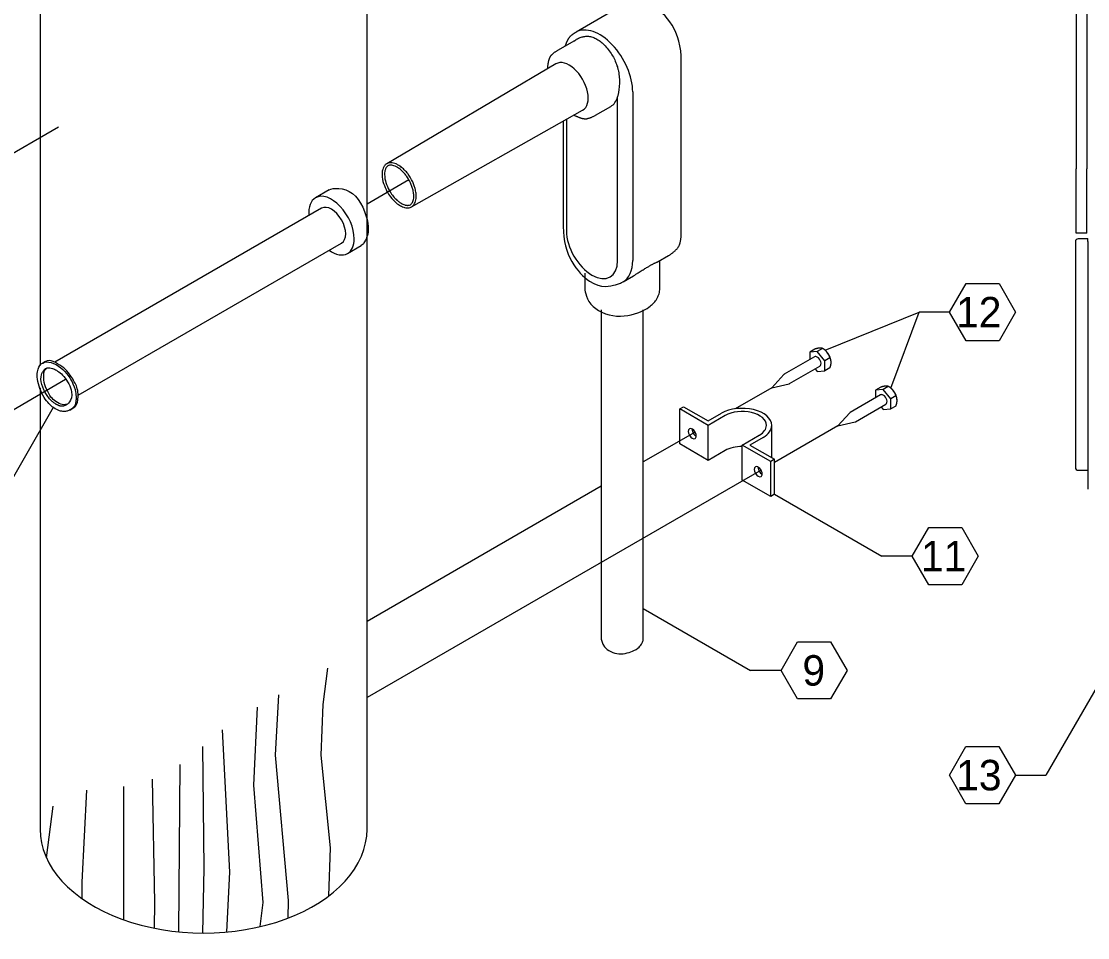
# Model space of a CAD drawing. Extents: x 99862 to 103151, y 100000 to 105076.
# Drawn here: x 100805 to 101365, y 104347 to 104827 of the extents above; entities that cross this region are included whole.
import ezdxf

# ---------------------------------------------------------------- set-up
doc = ezdxf.new("R2010")
doc.units = 0
for name, color, linetype in [('Level 13', 7, 'Continuous'), ('Level 15', 7, 'Continuous'), ('Level 16', 7, 'Continuous'), ('Level 20', 7, 'Continuous'), ('Level 21', 7, 'Continuous'), ('Level 23', 7, 'Continuous'), ('Level 27', 7, 'Continuous'), ('Level 28', 7, 'Continuous'), ('Level 31', 7, 'Continuous'), ('Level 33', 7, 'Continuous'), ('Level 41', 7, 'Continuous')]:
    doc.layers.add(name, color=color, linetype=linetype)

msp = doc.modelspace()

# ---------------------------------------------------------------- linework, layer by layer
at = {"layer": 'Level 13'}
for p, q in [((101120.49, 104835.56), (101096.62, 104821.78)), ((101095.44, 104817.14), (101087.15, 104812.36)), ((101151.84, 104718.09), (101151.84, 104806.5)), ((101118.81, 104790.2), (101118.38, 104787.89)), ((101118.38, 104702.01), (101118.38, 104787.89)), ((101126.33, 104790.43), (101126.33, 104702.01)), ((101106.84, 104778.26), (101114.79, 104782.85)), ((101091.53, 104775.91), (101091.53, 104717.52)), ((101089.88, 104774.96), (101089.88, 104719.81)), ((101139.65, 104701.38), (101145.1, 104704.53)), ((101145.14, 104704.55), (101145.62, 104704.85)), ((101145.62, 104704.85), (101145.79, 104704.96)), ((101140.55, 104687.37), (101140.55, 104701.9)), ((101101.17, 104695.41), (101101.17, 104687.37)), ((101121.23, 104690.75), (101126.71, 104693.91)), ((101140.55, 104687.18), (101140.55, 104687.38))]:
    msp.add_line(p, q, dxfattribs=at)
for centre, major_axis, start_param, end_param in [((101108.93, 104800.47), (-12.3, 21.31), 3.926991, 6.282516), ((101093.02, 104793.01), (7.03, -12.18), 6.283185, 9.424778), ((101104.95, 104799.9), (9.84, -17.05), 0, 0.517335), ((101104.95, 104709.76), (9.49, -16.44), 3.926991, 7.068583), ((101108.93, 104712.06), (-12.3, 21.31), 3.140924, 3.926991)]:
    msp.add_ellipse(centre, major_axis=major_axis, ratio=0.57735, start_param=start_param, end_param=end_param, dxfattribs=at)
for points, degree in [([(101151.84, 104806.5), (101152.06, 104822.03), (101135.62, 104841.83), (101121.8, 104836.21), (101121.6, 104836.13)], 3), ([(101096.64, 104821.79), (101093.88, 104820.23), (101091.88, 104817.56), (101090.86, 104814.51)], 2), ([(101095.44, 104817.14), (101104.39, 104823.57), (101121.18, 104803.6), (101118.81, 104790.2)], 2), ([(101087.13, 104812.34), (101083.69, 104810.37), (101081.82, 104806.61), (101081.48, 104802.59)], 2), ([(101095.54, 104778.23), (101099.2, 104776.49), (101103.16, 104776.22), (101106.84, 104778.25)], 2), ([(101089.88, 104719.81), (101089.69, 104704.95), (101105.07, 104685.67), (101119.4, 104689.86), (101120.41, 104690.33), (101120.93, 104690.58)], 3), ([(101145.79, 104704.96), (101149.92, 104707.73), (101151.89, 104712.77), (101151.84, 104718.09)], 2), ([(101126.71, 104693.91), (101132.46, 104697.57), (101138.16, 104700.87), (101139.67, 104701.39)], 2), ([(101101.17, 104687.37), (101101.16, 104687.06), (101101.79, 104678.11), (101117.89, 104670.7), (101133.74, 104675.82), (101137.87, 104680.23), (101138.84, 104681.55), (101139.62, 104682.97), (101140.18, 104684.49), (101140.48, 104685.93), (101140.53, 104686.83), (101140.55, 104687.18)], 3)]:
    msp.add_open_spline(points, degree=degree, dxfattribs=at)
at = {"layer": 'Level 15'}
for p, q in [((101227.28, 104654.9), (101276.7, 104674.85)), ((101261.9, 104634.91), (101276.7, 104674.85)), ((101292.7, 104674.85), (101276.7, 104674.85)), ((100822.1, 104624.87), (100721.67, 104450.91)), ((101200.74, 104579.29), (101257.03, 104546.79)), ((101426.72, 104576.54), (101343.2, 104431.88)), ((101273.03, 104546.79), (101257.03, 104546.79)), ((101131.89, 104519.34), (101188.19, 104486.84)), ((101131.89, 104519.34), (101188.19, 104486.84)), ((101204.19, 104486.84), (101188.19, 104486.84)), ((101204.19, 104486.84), (101188.19, 104486.84)), ((101327.2, 104431.88), (101343.2, 104431.88))]:
    msp.add_line(p, q, dxfattribs=at)
at = {"layer": 'Level 16'}
for p, q in [((100824.93, 104771.97), (100695.86, 104697.45)), ((101008.83, 104744.29), (100986.88, 104731.52)), ((100828.58, 104639.5), (100696.72, 104562.84)), ((101199.34, 104635.21), (101180.15, 104624.13)), ((101233.96, 104615.22), (101200.74, 104596.04)), ((101159.05, 104611.95), (101131.89, 104596.27)), ((101193.67, 104591.96), (100986.88, 104472.57)), ((101109.75, 104583.48), (100986.88, 104512.55))]:
    msp.add_line(p, q, dxfattribs=at)
at = {"layer": 'Level 20'}
for points in [[(101292.7, 104674.85), (101301.36, 104689.85), (101318.68, 104689.85), (101327.33, 104674.85), (101318.68, 104659.85), (101301.36, 104659.85), (101292.7, 104674.85)], [(101273.03, 104546.79), (101281.69, 104561.79), (101299.01, 104561.79), (101307.66, 104546.79), (101299.01, 104531.79), (101281.69, 104531.79), (101273.03, 104546.79)], [(101204.19, 104486.84), (101212.85, 104501.83), (101230.17, 104501.83), (101238.81, 104486.84), (101230.17, 104471.84), (101212.85, 104471.84), (101204.19, 104486.84)], [(101292.58, 104431.88), (101301.24, 104446.88), (101318.56, 104446.88), (101327.2, 104431.88), (101318.56, 104416.89), (101301.24, 104416.89), (101292.58, 104431.88)]]:
    msp.add_lwpolyline(points, dxfattribs=at)
at = {"layer": 'Level 21'}
for p, q in [((100966.92, 104739.02), (100959.77, 104734.89)), ((100962.93, 104729.41), (100822.99, 104648.61)), ((100835.21, 104631.31), (100973.48, 104711.14)), ((100976.64, 104705.66), (100983.8, 104709.79))]:
    msp.add_line(p, q, dxfattribs=at)
for major_axis, start_param, end_param in [((8.44, -14.61), 0.785398, 3.141593), ((8.44, -14.61), 3.141593, 4.037256), ((-5.27, 9.13), 3.141593, 6.283185), ((8.44, -14.61), 0, 0.785398), ((8.44, -14.61), 5.387519, 6.283185)]:
    msp.add_ellipse((100968.21, 104720.27), major_axis=major_axis, ratio=0.57735, start_param=start_param, end_param=end_param, dxfattribs=at)
msp.add_open_spline([(100966.92, 104739.02), (100968.8, 104740.12), (100980.76, 104741.03), (100989.3, 104719.13), (100985.55, 104711.6), (100984.81, 104710.48), (100984.11, 104710), (100983.8, 104709.79)], degree=3, dxfattribs=at)
at = {"layer": 'Level 23'}
for p, q in [((100817.7, 104648.77), (100816.61, 104648.14)), ((100830.84, 104623.5), (100831.93, 104624.13))]:
    msp.add_line(p, q, dxfattribs=at)
for points, degree in [([(100830.84, 104623.5), (100830.56, 104623.34), (100829.49, 104622.84), (100827.76, 104622.6), (100825.49, 104622.99), (100822.65, 104624.23), (100817.12, 104629.04), (100812.83, 104640.49), (100814.61, 104646.86), (100816.46, 104648.04), (100816.6, 104648.13), (100816.61, 104648.14)], 3), ([(100816.61, 104648.14), (100818.92, 104649.62), (100827.02, 104646.68), (100833.5, 104636.4), (100834.03, 104631.58), (100834.11, 104630.88), (100834.12, 104630.43), (100834.12, 104630.21)], 3), ([(100835.22, 104630.84), (100835.22, 104633.91), (100833.96, 104637.45), (100829.89, 104643.66), (100827.11, 104646.34), (100821.85, 104649.38), (100819.4, 104649.75), (100817.7, 104648.77)], 3), ([(100823.39, 104626.69), (100822.95, 104626.94), (100822.31, 104627.38), (100820.85, 104628.63), (100819.72, 104629.97), (100816.19, 104635.36), (100815.28, 104641.43), (100817.03, 104644.18), (100817.34, 104644.6), (100817.7, 104644.95), (100817.98, 104645.13), (100818.12, 104645.21)], 3), ([(100817.14, 104640.95), (100817.14, 104642.99), (100817.7, 104644.59), (100818.7, 104645.48)], 2), ([(100829.58, 104626.62), (100828.12, 104626.05), (100826.28, 104626.28), (100822.44, 104628.49), (100820.53, 104630.67), (100817.89, 104635.73), (100817.14, 104638.59), (100817.14, 104640.95)], 3), ([(100818.12, 104645.22), (100818.67, 104645.54), (100819.73, 104645.77), (100822.21, 104645.34), (100827.82, 104642.15), (100833.08, 104632.27), (100830.59, 104627.18), (100829.12, 104626.3), (100829.06, 104626.26)], 3), ([(100834.12, 104630.21), (100834.14, 104627.17), (100832.9, 104624.69), (100830.87, 104623.52)], 2), ([(100831.92, 104624.13), (100831.92, 104624.13), (100831.92, 104624.13), (100831.92, 104624.13), (100833.95, 104625.3), (100835.22, 104627.77), (100835.22, 104630.84)], 3), ([(100829.06, 104626.26), (100827.53, 104625.37), (100825.42, 104625.51), (100823.39, 104626.69)], 2)]:
    msp.add_open_spline(points, degree=degree, dxfattribs=at)
at = {"layer": 'Level 27'}
for p, q in [((101085.99, 104805.19), (100997.2, 104752.77)), ((101010.27, 104730.15), (101100.05, 104780.83)), ((101109.75, 104676), (101109.75, 104503.53)), ((101131.89, 104503.68), (101131.89, 104676))]:
    msp.add_line(p, q, dxfattribs=at)
for points in [[(100997.2, 104752.77), (100996.84, 104752.56), (100996.51, 104752.29), (100995.93, 104751.62), (100995.67, 104751.21), (100995.04, 104749.81), (100994.79, 104748.61), (100994.79, 104747.2)], [(101010.27, 104730.15), (101010.64, 104730.36), (101010.97, 104730.64), (101011.55, 104731.31), (101011.8, 104731.72), (101012.43, 104733.12), (101012.68, 104734.31), (101012.68, 104736.39), (101012.62, 104737.13), (101012.38, 104738.67), (101012.2, 104739.49), (101011.48, 104741.9), (101010.77, 104743.51), (101009.03, 104746.53), (101007.98, 104747.95), (101006.25, 104749.78), (101005.64, 104750.34), (101004.42, 104751.32), (101003.81, 104751.74), (101002.02, 104752.78), (101000.86, 104753.17), (100999.33, 104753.32), (100998.85, 104753.3), (100997.98, 104753.13), (100997.57, 104752.99), (100997.2, 104752.77)], [(100994.79, 104747.2), (100994.79, 104745.1), (100995.34, 104742.66), (100997.43, 104737.84), (100998.92, 104735.56), (101002.38, 104731.91), (101004.27, 104730.62), (101006.87, 104729.72), (101007.67, 104729.6), (101009.09, 104729.66), (101009.72, 104729.83), (101010.27, 104730.15)], [(100997.85, 104751.65), (100997.61, 104751.52), (100997.4, 104751.34), (100996.99, 104750.87), (100996.8, 104750.58), (100996.3, 104749.48), (100996.08, 104748.46), (100996.08, 104747.2)], [(100996.08, 104747.2), (100996.08, 104745.33), (100996.58, 104743.04), (100998.55, 104738.5), (100999.98, 104736.33), (101002.4, 104733.77), (101003.24, 104733.05), (101004.89, 104731.91), (101005.69, 104731.5), (101006.79, 104731.12), (101007.14, 104731.03), (101007.78, 104730.92), (101008.07, 104730.91), (101008.86, 104730.94), (101009.26, 104731.06), (101009.62, 104731.27)], [(101009.62, 104731.27), (101009.86, 104731.41), (101010.08, 104731.58), (101010.48, 104732.05), (101010.67, 104732.35), (101011.16, 104733.44), (101011.38, 104734.46), (101011.39, 104736.32), (101011.34, 104736.99), (101011.11, 104738.41), (101010.94, 104739.17), (101010.27, 104741.42), (101009.61, 104742.95), (101007.96, 104745.8), (101006.97, 104747.14), (101005.35, 104748.85), (101004.79, 104749.38), (101003.66, 104750.28), (101003.11, 104750.66), (101001.5, 104751.58), (101000.5, 104751.9), (100999.31, 104752.02), (100998.96, 104752.01), (100998.35, 104751.89), (100998.09, 104751.8), (100997.85, 104751.65)], [(101109.75, 104503.78), (101109.74, 104503.61), (101110.09, 104498.57), (101119.15, 104494.4), (101128.06, 104497.29), (101130.39, 104499.77), (101130.93, 104500.51), (101131.37, 104501.31), (101131.69, 104502.16), (101131.86, 104502.97), (101131.88, 104503.48), (101131.89, 104503.68)]]:
    msp.add_open_spline(points, degree=3, dxfattribs=at)
at = {"layer": 'Level 28'}
for p, q in [((101221.9, 104655.48), (101219.23, 104653.94)), ((101223.2, 104654.29), (101219.23, 104653.94)), ((101219.23, 104653.94), (101219.23, 104649.94)), ((101225.88, 104655.84), (101223.2, 104654.29)), ((101227.18, 104649.35), (101223.2, 104654.29)), ((101221.8, 104651.43), (101205.89, 104642.24)), ((101208.7, 104637.37), (101224.61, 104646.55)), ((101229.85, 104650.89), (101227.18, 104649.35)), ((101227.18, 104644.04), (101227.18, 104649.35)), ((101205.66, 104642.06), (101199.34, 104635.21)), ((101222.08, 104645.09), (101223.2, 104643.69)), ((101223.2, 104643.69), (101227.18, 104644.04)), ((101229.85, 104645.58), (101227.18, 104644.04)), ((101199.34, 104635.21), (101208.43, 104637.26)), ((101256.52, 104635.49), (101253.85, 104633.95)), ((101260.5, 104635.85), (101257.83, 104634.3)), ((101256.42, 104631.44), (101240.51, 104622.25)), ((101257.83, 104634.3), (101253.85, 104633.95)), ((101253.85, 104633.95), (101253.85, 104629.95)), ((101261.8, 104629.36), (101257.83, 104634.3)), ((101264.47, 104630.9), (101261.8, 104629.36)), ((101151.02, 104624.07), (101153.01, 104625.22)), ((101165.94, 104615.46), (101151.02, 104624.07)), ((101151.02, 104605.7), (101151.02, 104624.07)), ((101153.01, 104625.22), (101165.94, 104617.75)), ((101243.32, 104617.38), (101259.23, 104626.57)), ((101256.7, 104625.1), (101257.83, 104623.7)), ((101257.83, 104623.7), (101261.8, 104624.05)), ((101261.8, 104624.05), (101261.8, 104629.36)), ((101264.47, 104625.6), (101261.8, 104624.05)), ((101165.94, 104617.75), (101172.9, 104621.77)), ((101174.89, 104620.62), (101165.94, 104615.46)), ((101240.28, 104622.07), (101233.96, 104615.22)), ((101165.94, 104597.09), (101165.94, 104615.46)), ((101199.3, 104598.49), (101199.3, 104615.46)), ((101233.96, 104615.22), (101243.05, 104617.28)), ((101183.84, 104605.12), (101192.79, 104610.29)), ((101194.77, 104609.14), (101187.81, 104605.12)), ((101165.94, 104597.09), (101151.02, 104605.7)), ((101174.89, 104602.25), (101165.94, 104597.09)), ((101183.84, 104586.75), (101183.84, 104605.12)), ((101198.75, 104596.51), (101183.84, 104605.12)), ((101187.81, 104605.12), (101200.74, 104597.66)), ((101200.74, 104597.66), (101198.75, 104596.51)), ((101198.75, 104578.14), (101198.75, 104596.51)), ((101200.74, 104579.29), (101200.74, 104597.66)), ((101198.75, 104578.14), (101183.84, 104586.75)), ((101200.74, 104579.29), (101198.75, 104578.14))]:
    msp.add_line(p, q, dxfattribs=at)
for centre, major_axis, start_param, end_param in [((101226.49, 104650.89), (2.81, -4.87), 0.785398, 1.832596), ((101223.2, 104648.99), (1.41, -2.44), 2.356194, 3.141593), ((101223.2, 104648.99), (1.41, -2.44), 0, 2.356194), ((101207.29, 104639.8), (1.41, -2.44), 3.141593, 3.319303), ((101207.29, 104639.8), (1.41, -2.44), 6.105475, 6.283185), ((101257.83, 104629), (1.41, -2.44), 2.356194, 3.141593), ((101257.83, 104629), (1.41, -2.44), 6.283185, 8.63938), ((101261.11, 104630.9), (2.81, -4.87), 0.785398, 1.832596), ((101183.84, 104615.46), (15.47, 0), 0, 2.356194), ((101183.84, 104615.46), (-12.66, 0), 3.141593, 5.497787), ((101241.92, 104619.82), (1.41, -2.44), 3.141593, 3.319303), ((101157.58, 104611.1), (1.48, -2.56), 3.141593, 6.283185), ((101157.58, 104611.1), (1.48, -2.56), 0.785398, 3.141593), ((101159.56, 104612.25), (-1.48, 2.56), 0.738434, 0.785398), ((101159.56, 104612.25), (-1.48, 2.56), 0.785398, 2.403158), ((101183.84, 104615.46), (-12.66, 0), 2.356194, 3.141593), ((101183.84, 104615.46), (15.47, 0), 5.497787, 6.283185), ((101241.92, 104619.82), (1.41, -2.44), 6.105475, 6.283185), ((101157.58, 104611.1), (1.48, -2.56), 6.283185, 7.068583), ((101183.84, 104597.09), (-12.66, 0), 4.712389, 5.497787), ((101192.2, 104591.11), (1.48, -2.56), 3.141593, 6.283185), ((101192.2, 104591.11), (1.48, -2.56), 0.785398, 3.141593), ((101194.19, 104592.26), (-1.48, 2.56), 0.738434, 0.785398), ((101194.19, 104592.26), (-1.48, 2.56), 0.785398, 2.403158), ((101192.2, 104591.11), (1.48, -2.56), 0, 0.785398)]:
    msp.add_ellipse(centre, major_axis=major_axis, ratio=0.57735, start_param=start_param, end_param=end_param, dxfattribs=at)
for points in [[(101224.5, 104656.01), (101223.77, 104655.94), (101222.91, 104655.76), (101221.9, 104655.48)], [(101225.88, 104655.84), (101225.67, 104655.98), (101225.29, 104656.04), (101224.5, 104656.01)], [(101228.48, 104653.72), (101227.75, 104654.58), (101226.89, 104655.29), (101225.88, 104655.84)], [(101229.85, 104650.89), (101229.65, 104651.76), (101229.26, 104652.59), (101228.72, 104653.4)], [(101230.47, 104648.59), (101230.39, 104649.48), (101230.27, 104650.32), (101229.85, 104650.89)], [(101229.85, 104645.58), (101230.18, 104646.56), (101230.45, 104647.51), (101230.47, 104648.59)], [(101259.12, 104636.02), (101258.39, 104635.95), (101257.53, 104635.77), (101256.52, 104635.49)], [(101260.5, 104635.85), (101260.29, 104635.99), (101259.91, 104636.06), (101259.12, 104636.02)], [(101263.1, 104633.73), (101262.37, 104634.59), (101261.51, 104635.3), (101260.5, 104635.85)], [(101264.47, 104630.9), (101264.27, 104631.77), (101263.88, 104632.6), (101263.34, 104633.41)], [(101265.09, 104628.6), (101265.01, 104629.49), (101264.89, 104630.33), (101264.47, 104630.9)], [(101264.47, 104625.6), (101264.8, 104626.57), (101265.07, 104627.53), (101265.09, 104628.6)]]:
    msp.add_open_spline(points, degree=2, dxfattribs=at)
at = {"layer": 'Level 31'}
for p, q in [((100815.22, 105009.95), (100815.22, 104646.8)), ((100986.88, 104403.51), (100986.88, 105009.95)), ((100815.22, 104635.07), (100815.22, 104403.51))]:
    msp.add_line(p, q, dxfattribs=at)
for points in [[(100966.84, 104368.5), (100967.67, 104393.71), (100962.87, 104442.43), (100963.83, 104468.91), (100966.23, 104487.95)], [(100945.4, 104356.84), (100945.66, 104366.07), (100938.87, 104442.43), (100940.5, 104474.04)], [(100930.81, 104352.38), (100932.33, 104365.05), (100927.36, 104426.55), (100929.39, 104467.59)], [(100913.29, 104349.56), (100914.88, 104381), (100911.05, 104455.64)], [(100900.62, 104349), (100901.38, 104383.12), (100900.67, 104446.85)], [(100888.1, 104349.62), (100888.77, 104437.46)], [(100875.37, 104351.5), (100875.47, 104365.11), (100874.31, 104429.79)], [(100837.28, 104367.02), (100837.4, 104375.7), (100839.85, 104423.95)], [(100859.15, 104355.93), (100859.15, 104425.97)], [(100818.54, 104388.49), (100822.03, 104415.56)]]:
    msp.add_lwpolyline(points, dxfattribs=at)
msp.add_ellipse((100901.05, 104403.51), major_axis=(85.83, 0), ratio=0.635085, start_param=3.14158, end_param=6.283185, dxfattribs=at)
at = {"layer": 'Level 33'}
for p, q in [((101365.15, 104711.9), (101365.15, 104713.46)), ((101358.71, 104711.9), (101358.71, 104708.44)), ((101358.73, 104708.44), (101358.73, 104593.31)), ((101365.15, 104713.3), (101360.12, 104713.3)), ((101365.15, 104711.9), (101365.15, 104659.4)), ((101365.15, 104659.4), (101365.15, 104591.08)), ((101360.13, 104591.9), (101365.15, 104591.9)), ((101365.15, 104591.08), (101365.15, 104582.84)), ((101365.15, 104582.84), (101365.15, 104581.9))]:
    msp.add_line(p, q, dxfattribs=at)
for centre, start, end in [((101360.12, 104711.9), 90, 180), ((101360.13, 104593.31), 180, 270)]:
    msp.add_arc(centre, 1.41, start, end, dxfattribs=at)
at = {"layer": 'Level 41'}
for p, q in [((101359.17, 105031.74), (101359.17, 104750.04)), ((101364.79, 105031.74), (101364.79, 104750.04)), ((101359.17, 104716.29), (101359.17, 104750.04)), ((101364.79, 104716.29), (101364.79, 104750.04)), ((101364.79, 104716.29), (101359.17, 104716.29))]:
    msp.add_line(p, q, dxfattribs=at)

# ---------------------------------------------------------------- texts
at = {"layer": 'Level 20'}
for s, p in [('12', (101296.08, 104666.85)), ('11', (101277.62, 104538.79)), ('9', (101215.41, 104478.84)), ('13', (101296.12, 104423.88))]:
    msp.add_text(s, height=16, dxfattribs=at).set_placement(p)

doc.saveas('drawing.dxf')
